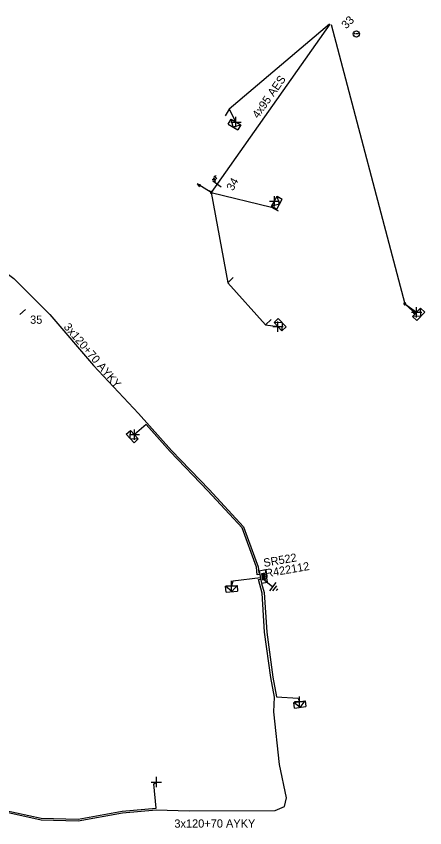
# Model space of a CAD drawing. Extents: x -540247 to -537390, y -1183890 to -1180355.
# Drawn here: x -537857 to -537807.3, y -1180518 to -1180419.2 of the extents above; entities that cross this region are included whole.
import ezdxf

# ---------------------------------------------------------------- set-up
doc = ezdxf.new("R2010")
doc.units = 0
for name, color, linetype in [('Vrstva 1', 7, 'Continuous'), ('Vrstva 10', 7, 'Continuous'), ('Vrstva 13', 7, 'Continuous'), ('Vrstva 14', 7, 'Continuous'), ('Vrstva 15', 7, 'Continuous'), ('Vrstva 18', 7, 'Continuous'), ('Vrstva 2', 7, 'Continuous'), ('Vrstva 28', 7, 'Continuous'), ('Vrstva 29', 7, 'Continuous'), ('Vrstva 30', 7, 'Continuous'), ('Vrstva 31', 7, 'Continuous'), ('Vrstva 34', 7, 'Continuous'), ('Vrstva 36', 7, 'Continuous'), ('Vrstva 4', 7, 'Continuous'), ('Vrstva 5', 7, 'Continuous'), ('Vrstva 50', 7, 'Continuous'), ('Vrstva 51', 7, 'Continuous'), ('Vrstva 52', 7, 'Continuous'), ('Vrstva 6', 7, 'Continuous'), ('Vrstva 8', 7, 'Continuous'), ('Vrstva 9', 7, 'Continuous')]:
    doc.layers.add(name, color=color, linetype=linetype)

# ---------------------------------------------------------------- blocks, each defined once
blk = doc.blocks.new('NN560')
at = {"layer": 'Vrstva 2'}
for points in [[(1.999, -0.001), (1.59, 0.141)], [(0, -0.001), (1.999, -0.001)], [(1.999, -0.001), (1.59, -0.134)]]:
    blk.add_lwpolyline(points, dxfattribs=at)
blk = doc.blocks.new('NN840')
at = {"layer": 'Vrstva 15'}
for points in [[(0.003, 0.619), (0.003, -0.631)], [(-0.745, -0.71), (-0.745, -0.66)], [(-0.73, -0.764), (-0.745, -0.71)], [(-0.657, -0.798), (-0.73, -0.764)], [(-0.627, -0.798), (-0.657, -0.798)], [(-0.558, -0.764), (-0.627, -0.798)], [(-0.538, -0.71), (-0.558, -0.764)], [(-0.538, -0.385), (-0.538, -0.71)], [(-0.332, -0.385), (-0.332, -0.798)], [(-0.332, -0.641), (-0.125, -0.385)], [(-0.263, -0.557), (-0.091, -0.798)]]:
    blk.add_lwpolyline(points, dxfattribs=at)
blk = doc.blocks.new('NN770')
at = {"layer": 'Vrstva 10'}
for p, q in [((0.002, 0.187), (0.002, 0.263)), ((0.002, -0.276), (0.002, 0.111))]:
    blk.add_line(p, q, dxfattribs=at)
blk.add_circle((0, -0.008), 0.375, dxfattribs=at)
blk = doc.blocks.new('NN800')
at = {"layer": 'Vrstva 1'}
for points in [[(-0.442, 0.442), (0.442, -0.442)], [(-0.442, -0.442), (0.442, 0.442)]]:
    blk.add_lwpolyline(points, dxfattribs=at)
blk = doc.blocks.new('NN620')
at = {"layer": 'Vrstva 8'}
for points in [[(0.752, 0.004), (-0.748, 0.004)], [(-0.748, 0.004), (-0.748, -0.746)], [(0.752, -0.746), (0.752, 0.004)], [(-0.748, -0.746), (0.752, -0.746)], [(0.368, -0.18), (-0.376, -0.18)], [(-0.376, -0.18), (-0.376, -0.558)], [(-0.376, -0.558), (0.368, -0.558)], [(0.321, -0.227), (-0.329, -0.227)], [(-0.329, -0.227), (-0.329, -0.51)], [(-0.329, -0.51), (0.321, -0.51)], [(0.274, -0.274), (-0.281, -0.274)], [(-0.281, -0.274), (-0.281, -0.463)], [(-0.281, -0.463), (0.274, -0.463)], [(0.227, -0.321), (-0.234, -0.321)], [(-0.234, -0.321), (-0.234, -0.416)], [(-0.234, -0.416), (0.227, -0.416)], [(-0.193, -0.369), (0.185, -0.369)], [(0.227, -0.416), (0.227, -0.321)], [(0.274, -0.463), (0.274, -0.274)], [(0.321, -0.51), (0.321, -0.227)], [(0.368, -0.558), (0.368, -0.18)]]:
    blk.add_lwpolyline(points, dxfattribs=at)
blk = doc.blocks.new('NN630')
at = {"layer": 'Vrstva 9'}
for points in [[(-0.003, -0.7), (-0.703, 0)], [(-0.703, -0.7), (-0.703, 0), (0.697, 0), (0.697, -0.7)], [(-0.703, -0.7), (0.697, -0.7)], [(-0.003, -0.7), (0.697, 0)]]:
    blk.add_lwpolyline(points, dxfattribs=at)
blk = doc.blocks.new('NN810')
at = {"layer": 'Vrstva 14'}
for points in [[(0.004, -0.64), (0.004, -1.89)], [(0.629, -1.89), (-0.621, -1.89)], [(0.388, -2.2), (-0.399, -2.2)], [(0.004, -2.515), (-0.124, -2.515)], [(0.137, -2.515), (0.004, -2.515)]]:
    blk.add_lwpolyline(points, dxfattribs=at)
blk = doc.blocks.new('NN500')
at = {"layer": 'Vrstva 2'}
for points in [[(0, -0.24), (0.02, -0.23), (0.05, -0.23), (0.07, -0.22), (0.09, -0.22), (0.12, -0.2), (0.14, -0.19), (0.16, -0.18), (0.17, -0.16), (0.19, -0.14), (0.2, -0.12), (0.21, -0.1), (0.22, -0.07), (0.23, -0.05), (0.23, -0.02), (0.23, 0), (0.23, 0.02), (0.23, 0.05), (0.22, 0.07), (0.21, 0.1), (0.2, 0.12), (0.19, 0.14), (0.17, 0.16), (0.16, 0.17), (0.14, 0.19), (0.12, 0.2), (0.09, 0.21), (0.07, 0.22), (0.05, 0.23), (0.02, 0.23), (0, 0.23), (-0.03, 0.23), (-0.05, 0.23), (-0.07, 0.22), (-0.1, 0.21), (-0.12, 0.2), (-0.14, 0.19), (-0.16, 0.17), (-0.18, 0.16), (-0.19, 0.14), (-0.2, 0.12), (-0.22, 0.1), (-0.22, 0.07), (-0.23, 0.05), (-0.23, 0.02), (-0.24, 0), (-0.23, -0.02), (-0.23, -0.05), (-0.22, -0.07), (-0.22, -0.1), (-0.2, -0.12), (-0.19, -0.14), (-0.18, -0.16), (-0.16, -0.18), (-0.14, -0.19), (-0.12, -0.2), (-0.1, -0.22), (-0.07, -0.22), (-0.05, -0.23), (-0.03, -0.23), (0, -0.24)], [(0, -0.24), (0.02, -0.23), (0.05, -0.23), (0.07, -0.22), (0.09, -0.22), (0.12, -0.2), (0.14, -0.19), (0.16, -0.18), (0.17, -0.16), (0.19, -0.14), (0.2, -0.12), (0.21, -0.1), (0.22, -0.07), (0.23, -0.05), (0.23, -0.02), (0.23, 0), (0.23, 0.02), (0.23, 0.05), (0.22, 0.07), (0.21, 0.1), (0.2, 0.12), (0.19, 0.14), (0.17, 0.16), (0.16, 0.17), (0.14, 0.19), (0.12, 0.2), (0.09, 0.21), (0.07, 0.22), (0.05, 0.23), (0.02, 0.23), (0, 0.23), (-0.03, 0.23), (-0.05, 0.23), (-0.07, 0.22), (-0.1, 0.21), (-0.12, 0.2), (-0.14, 0.19), (-0.16, 0.17), (-0.18, 0.16), (-0.19, 0.14), (-0.2, 0.12), (-0.22, 0.1), (-0.22, 0.07), (-0.23, 0.05), (-0.23, 0.02), (-0.24, 0), (-0.23, -0.02), (-0.23, -0.05), (-0.22, -0.07), (-0.22, -0.1), (-0.2, -0.12), (-0.19, -0.14), (-0.18, -0.16), (-0.16, -0.18), (-0.14, -0.19), (-0.12, -0.2), (-0.1, -0.22), (-0.07, -0.22), (-0.05, -0.23), (-0.03, -0.23), (0, -0.24)], [(0, -0.21), (0.02, -0.2), (0.04, -0.2), (0.06, -0.2), (0.08, -0.19), (0.1, -0.18), (0.12, -0.17), (0.14, -0.15), (0.15, -0.14), (0.16, -0.12), (0.18, -0.1), (0.19, -0.08), (0.19, -0.06), (0.2, -0.04), (0.2, -0.02), (0.2, 0), (0.2, 0.02), (0.2, 0.04), (0.19, 0.06), (0.19, 0.08), (0.18, 0.1), (0.16, 0.12), (0.15, 0.14), (0.14, 0.15), (0.12, 0.17), (0.1, 0.18), (0.08, 0.19), (0.06, 0.19), (0.04, 0.2), (0.02, 0.2), (0, 0.2), (-0.02, 0.2), (-0.04, 0.2), (-0.06, 0.19), (-0.08, 0.19), (-0.1, 0.18), (-0.12, 0.17), (-0.14, 0.15), (-0.15, 0.14), (-0.17, 0.12), (-0.18, 0.1), (-0.19, 0.08), (-0.2, 0.06), (-0.2, 0.04), (-0.21, 0.02), (-0.21, 0), (-0.21, -0.02), (-0.2, -0.04), (-0.2, -0.06), (-0.19, -0.08), (-0.18, -0.1), (-0.17, -0.12), (-0.15, -0.14), (-0.14, -0.15), (-0.12, -0.17), (-0.1, -0.18), (-0.08, -0.19), (-0.06, -0.2), (-0.04, -0.2), (-0.02, -0.2), (0, -0.21)], [(0, -0.18), (0.02, -0.18), (0.04, -0.17), (0.05, -0.17), (0.07, -0.16), (0.09, -0.15), (0.1, -0.14), (0.12, -0.13), (0.13, -0.12), (0.14, -0.1), (0.15, -0.09), (0.16, -0.07), (0.17, -0.05), (0.17, -0.04), (0.17, -0.02), (0.17, 0), (0.17, 0.02), (0.17, 0.04), (0.17, 0.05), (0.16, 0.07), (0.15, 0.09), (0.14, 0.1), (0.13, 0.12), (0.12, 0.13), (0.1, 0.14), (0.09, 0.15), (0.07, 0.16), (0.05, 0.17), (0.04, 0.17), (0.02, 0.17), (0, 0.18), (-0.02, 0.17), (-0.04, 0.17), (-0.06, 0.17), (-0.07, 0.16), (-0.09, 0.15), (-0.1, 0.14), (-0.12, 0.13), (-0.13, 0.12), (-0.14, 0.1), (-0.15, 0.09), (-0.16, 0.07), (-0.17, 0.05), (-0.17, 0.04), (-0.18, 0.02), (-0.18, 0), (-0.18, -0.02), (-0.17, -0.04), (-0.17, -0.05), (-0.16, -0.07), (-0.15, -0.09), (-0.14, -0.1), (-0.13, -0.12), (-0.12, -0.13), (-0.1, -0.14), (-0.09, -0.15), (-0.07, -0.16), (-0.06, -0.17), (-0.04, -0.17), (-0.02, -0.18), (0, -0.18)], [(0, -0.15), (0.01, -0.15), (0.03, -0.14), (0.04, -0.14), (0.06, -0.13), (0.07, -0.13), (0.08, -0.12), (0.1, -0.11), (0.11, -0.1), (0.12, -0.09), (0.13, -0.07), (0.13, -0.06), (0.14, -0.05), (0.14, -0.03), (0.14, -0.02), (0.14, 0), (0.14, 0.01), (0.14, 0.03), (0.14, 0.04), (0.13, 0.06), (0.13, 0.07), (0.12, 0.09), (0.11, 0.1), (0.1, 0.11), (0.08, 0.12), (0.07, 0.13), (0.06, 0.13), (0.04, 0.14), (0.03, 0.14), (0.01, 0.14), (0, 0.15), (-0.02, 0.14), (-0.03, 0.14), (-0.05, 0.14), (-0.06, 0.13), (-0.07, 0.13), (-0.09, 0.12), (-0.1, 0.11), (-0.11, 0.1), (-0.12, 0.09), (-0.13, 0.07), (-0.13, 0.06), (-0.14, 0.04), (-0.14, 0.03), (-0.15, 0.01), (-0.15, 0), (-0.15, -0.02), (-0.14, -0.03), (-0.14, -0.05), (-0.13, -0.06), (-0.13, -0.07), (-0.12, -0.09), (-0.11, -0.1), (-0.1, -0.11), (-0.09, -0.12), (-0.07, -0.13), (-0.06, -0.13), (-0.05, -0.14), (-0.03, -0.14), (-0.02, -0.15), (0, -0.15)], [(0, -0.12), (0.01, -0.12), (0.02, -0.11), (0.03, -0.11), (0.05, -0.11), (0.06, -0.1), (0.07, -0.09), (0.08, -0.09), (0.09, -0.08), (0.09, -0.07), (0.1, -0.06), (0.11, -0.05), (0.11, -0.04), (0.11, -0.02), (0.11, -0.01), (0.12, 0), (0.11, 0.01), (0.11, 0.02), (0.11, 0.04), (0.11, 0.05), (0.1, 0.06), (0.09, 0.07), (0.09, 0.08), (0.08, 0.09), (0.07, 0.09), (0.06, 0.1), (0.05, 0.11), (0.03, 0.11), (0.02, 0.11), (0.01, 0.12), (0, 0.12), (-0.01, 0.12), (-0.03, 0.11), (-0.04, 0.11), (-0.05, 0.11), (-0.06, 0.1), (-0.07, 0.09), (-0.08, 0.09), (-0.09, 0.08), (-0.1, 0.07), (-0.1, 0.06), (-0.11, 0.05), (-0.11, 0.04), (-0.12, 0.02), (-0.12, 0.01), (-0.12, 0), (-0.12, -0.01), (-0.12, -0.02), (-0.11, -0.04), (-0.11, -0.05), (-0.1, -0.06), (-0.1, -0.07), (-0.09, -0.08), (-0.08, -0.09), (-0.07, -0.09), (-0.06, -0.1), (-0.05, -0.11), (-0.04, -0.11), (-0.03, -0.11), (-0.01, -0.12), (0, -0.12)], [(0, -0.09), (0.01, -0.09), (0.02, -0.09), (0.03, -0.08), (0.03, -0.08), (0.04, -0.08), (0.05, -0.07), (0.06, -0.07), (0.06, -0.06), (0.07, -0.05), (0.07, -0.04), (0.08, -0.04), (0.08, -0.03), (0.08, -0.02), (0.09, -0.01), (0.09, 0), (0.09, 0.01), (0.08, 0.02), (0.08, 0.03), (0.08, 0.03), (0.07, 0.04), (0.07, 0.05), (0.06, 0.06), (0.06, 0.06), (0.05, 0.07), (0.04, 0.07), (0.03, 0.08), (0.03, 0.08), (0.02, 0.08), (0.01, 0.09), (0, 0.09), (-0.01, 0.09), (-0.02, 0.08), (-0.03, 0.08), (-0.04, 0.08), (-0.04, 0.07), (-0.05, 0.07), (-0.06, 0.06), (-0.07, 0.06), (-0.07, 0.05), (-0.08, 0.04), (-0.08, 0.03), (-0.08, 0.03), (-0.09, 0.02), (-0.09, 0.01), (-0.09, 0), (-0.09, -0.01), (-0.09, -0.02), (-0.08, -0.03), (-0.08, -0.04), (-0.08, -0.04), (-0.07, -0.05), (-0.07, -0.06), (-0.06, -0.07), (-0.05, -0.07), (-0.04, -0.08), (-0.04, -0.08), (-0.03, -0.08), (-0.02, -0.09), (-0.01, -0.09), (0, -0.09)], [(0, -0.06), (0, -0.06), (0.01, -0.06), (0.02, -0.05), (0.02, -0.05), (0.03, -0.05), (0.03, -0.05), (0.04, -0.04), (0.04, -0.04), (0.05, -0.03), (0.05, -0.03), (0.05, -0.02), (0.05, -0.02), (0.05, -0.01), (0.06, -0.01), (0.06, 0), (0.06, 0.01), (0.05, 0.01), (0.05, 0.02), (0.05, 0.02), (0.05, 0.03), (0.05, 0.03), (0.04, 0.04), (0.04, 0.04), (0.03, 0.05), (0.03, 0.05), (0.02, 0.05), (0.02, 0.05), (0.01, 0.06), (0, 0.06), (0, 0.06), (-0.01, 0.06), (-0.01, 0.06), (-0.02, 0.05), (-0.02, 0.05), (-0.03, 0.05), (-0.03, 0.05), (-0.04, 0.04), (-0.04, 0.04), (-0.05, 0.03), (-0.05, 0.03), (-0.05, 0.02), (-0.06, 0.02), (-0.06, 0.01), (-0.06, 0.01), (-0.06, 0), (-0.06, -0.01), (-0.06, -0.01), (-0.06, -0.02), (-0.05, -0.02), (-0.05, -0.03), (-0.05, -0.03), (-0.04, -0.04), (-0.04, -0.04), (-0.03, -0.05), (-0.03, -0.05), (-0.02, -0.05), (-0.02, -0.05), (-0.01, -0.06), (-0.01, -0.06), (0, -0.06)], [(0, -0.03), (0, -0.03), (0, -0.03), (0.01, -0.03), (0.01, -0.03), (0.01, -0.02), (0.02, -0.02), (0.02, -0.02), (0.02, -0.02), (0.02, -0.02), (0.02, -0.01), (0.02, -0.01), (0.03, -0.01), (0.03, -0.01), (0.03, 0), (0.03, 0), (0.03, 0), (0.03, 0.01), (0.03, 0.01), (0.02, 0.01), (0.02, 0.01), (0.02, 0.02), (0.02, 0.02), (0.02, 0.02), (0.02, 0.02), (0.01, 0.02), (0.01, 0.02), (0.01, 0.03), (0, 0.03), (0, 0.03), (0, 0.03), (0, 0.03), (-0.01, 0.03), (-0.01, 0.03), (-0.01, 0.02), (-0.02, 0.02), (-0.02, 0.02), (-0.02, 0.02), (-0.02, 0.02), (-0.02, 0.02), (-0.03, 0.01), (-0.03, 0.01), (-0.03, 0.01), (-0.03, 0.01), (-0.03, 0), (-0.03, 0), (-0.03, 0), (-0.03, -0.01), (-0.03, -0.01), (-0.03, -0.01), (-0.03, -0.01), (-0.02, -0.02), (-0.02, -0.02), (-0.02, -0.02), (-0.02, -0.02), (-0.02, -0.02), (-0.01, -0.03), (-0.01, -0.03), (-0.01, -0.03), (0, -0.03), (0, -0.03)], [(0.23, 0), (0.7, 0)]]:
    blk.add_lwpolyline(points, dxfattribs=at)
blk = doc.blocks.new('NN510')
at = {"layer": 'Vrstva 2'}
blk.add_lwpolyline([(0.001, 0.002), (0.001, 0.939)], dxfattribs=at)

msp = doc.modelspace()

# ---------------------------------------------------------------- linework, layer by layer
at = {"layer": 'Vrstva 4'}
for points in [[(-537818.884, -1180420.138), (-537831.082, -1180430.502), (-537830.253, -1180432.05)], [(-537818.663, -1180420.172), (-537809.71, -1180454.17), (-537808.264, -1180455.208)]]:
    msp.add_lwpolyline(points, dxfattribs=at)
at = {"layer": 'Vrstva 5'}
for points in [[(-537884.586, -1180432.61), (-537882.08, -1180433.9), (-537880.81, -1180434.99), (-537875.1, -1180439.06), (-537872.09, -1180441.05), (-537866.46, -1180444.78), (-537862.96, -1180446.83), (-537857.29, -1180451.1), (-537852.89, -1180455.49), (-537847.58, -1180461.71), (-537842.1, -1180467.52), (-537838.1, -1180472.04), (-537833.53, -1180476.8), (-537829.32, -1180481.34), (-537827.56, -1180486.21), (-537827.489, -1180486.953), (-537827.363, -1180486.926)], [(-537866.535, -1180513.177), (-537866.577, -1180514.907), (-537865.85, -1180515.36), (-537858.5, -1180516.01), (-537853.98, -1180517), (-537849.45, -1180517.13), (-537844.07, -1180516.16), (-537839.96, -1180515.78), (-537835.96, -1180515.9), (-537825.48, -1180515.88), (-537824.36, -1180515.37), (-537824.1, -1180514.31), (-537824.95, -1180510.27), (-537825.63, -1180503.87), (-537825.563, -1180502.073), (-537826.013, -1180499.69), (-537826.764, -1180494.172), (-537827.064, -1180489.391), (-537827.53, -1180487.764), (-537827.266, -1180487.689)]]:
    msp.add_lwpolyline(points, dxfattribs=at)
at = {"layer": 'Vrstva 50'}
msp.add_lwpolyline([(-537818.821, -1180420.147), (-537833.255, -1180440.612)], dxfattribs=at)
at = {"layer": 'Vrstva 52'}
for points in [[(-537827.321, -1180487.122), (-537827.667, -1180487.196), (-537827.757, -1180486.254), (-537829.494, -1180481.446), (-537833.675, -1180476.937), (-537838.247, -1180472.176), (-537841.175, -1180468.869), (-537842.608, -1180470.113)], [(-537827.272, -1180487.539), (-537830.632, -1180487.957), (-537830.809, -1180488.524)], [(-537827.141, -1180488.215), (-537826.816, -1180489.349), (-537826.516, -1180494.148), (-537825.767, -1180499.65), (-537825.317, -1180502.027), (-537822.678, -1180502.213), (-537822.52, -1180502.62)], [(-537866.335, -1180513.182), (-537866.374, -1180514.798), (-537865.785, -1180515.165), (-537858.47, -1180515.812), (-537853.956, -1180516.801), (-537849.465, -1180516.929), (-537844.097, -1180515.962), (-537839.966, -1180515.58), (-537840.238, -1180512.609), (-537839.947, -1180512.41)]]:
    msp.add_lwpolyline(points, dxfattribs=at)
at = {"layer": 'Vrstva 8'}
for points in [[(-537833.255, -1180440.612), (-537831.264, -1180451.625), (-537826.672, -1180456.737), (-537825.149, -1180456.955)], [(-537833.255, -1180440.612), (-537825.95, -1180442.414), (-537825.567, -1180441.692)]]:
    msp.add_lwpolyline(points, dxfattribs=at)

# ---------------------------------------------------------------- block references
at = {"layer": 'Vrstva 13'}
for name, p, rotation in [('NN510', (-537831.081, -1180430.502), 149.20328602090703), ('NN560', (-537833.256, -1180440.612), 149.28067207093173), ('NN510', (-537825.95, -1180442.413), -119.28188058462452), ('NN510', (-537831.265, -1180451.625), -45.20068887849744), ('NN560', (-537809.71, -1180454.17), -43.16770277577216), ('NN510', (-537855.879, -1180454.867), 132.18644449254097), ('NN510', (-537826.672, -1180456.737), -47.28672215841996)]:
    msp.add_blockref(name, p, dxfattribs=dict(at, rotation=rotation))
at = {"layer": 'Vrstva 13', "xscale": 0.5}
for p, yscale, rotation in [((-537833.255, -1180440.612), 0.5, 149.20700002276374), ((-537809.71, -1180454.17), 0.5000000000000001, -44.10400000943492)]:
    msp.add_blockref('NN500', p, dxfattribs=dict(at, yscale=yscale, rotation=rotation))
at = {"layer": 'Vrstva 15', "rotation": 52.02628610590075}
msp.add_blockref('NN810', (-537827.281, -1180487.454), dxfattribs=at)
at = {"layer": 'Vrstva 18', "rotation": -125.19533332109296}
msp.add_blockref('NN840', (-537832.563, -1180439.632), dxfattribs=at)
at = {"layer": 'Vrstva 28', "rotation": 99.86143057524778}
msp.add_blockref('NN620', (-537827.281, -1180487.453), dxfattribs=at)
at = {"layer": 'Vrstva 31'}
for p, rotation in [((-537830.253, -1180432.051), -30.782608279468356), ((-537825.567, -1180441.692), 60.71811948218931), ((-537808.264, -1180455.208), 45.89606664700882), ((-537825.149, -1180456.955), 132.7132777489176), ((-537842.608, -1180470.113), -47.62218052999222), ((-537830.809, -1180488.524), 3.9469666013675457), ((-537822.52, -1180502.62), 7.169327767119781)]:
    msp.add_blockref('NN630', p, dxfattribs=dict(at, rotation=rotation))
at = {"layer": 'Vrstva 34'}
for p, rotation in [((-537830.253, -1180432.05), 45), ((-537825.567, -1180441.691), 45), ((-537808.264, -1180455.208), 45), ((-537825.149, -1180456.955), 45), ((-537842.608, -1180470.113), 45), ((-537830.809, -1180488.524), 45), ((-537822.52, -1180502.619), 45.00000009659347), ((-537839.947, -1180512.41), 45)]:
    msp.add_blockref('NN800', p, dxfattribs=dict(at, rotation=rotation))
at = {"layer": 'Vrstva 36', "rotation": 90}
msp.add_blockref('NN770', (-537815.609, -1180421.325), dxfattribs=at)

# ---------------------------------------------------------------- texts
at = {"layer": 'Vrstva 14'}
for s, rotation, p in [('33', 45.014, (-537816.831, -1180420.781)), ('34', 61.135, (-537830.615, -1180440.5))]:
    msp.add_text(s, height=1, rotation=rotation, dxfattribs=at).set_placement(p)
msp.add_text('35', height=1, dxfattribs=at).set_placement((-537855.31, -1180456.612))
at = {"layer": 'Vrstva 29'}
msp.add_text('R422112', height=1, rotation=9.861, dxfattribs=at).set_placement((-537826.602, -1180487.504))
at = {"layer": 'Vrstva 30'}
msp.add_text('SR522', height=1, rotation=9.861, dxfattribs=at).set_placement((-537826.824, -1180486.224))
at = {"layer": 'Vrstva 51'}
msp.add_text('4x95 AES', height=1, rotation=54.805, dxfattribs=at).set_placement((-537827.561, -1180431.691))
at = {"layer": 'Vrstva 6'}
for rotation, p in [(310.487, (-537851.289, -1180457.035)), (0.109, (-537837.752, -1180517.958))]:
    msp.add_text('3x120+70 AYKY', height=1, rotation=rotation, dxfattribs=at).set_placement(p)

doc.saveas('drawing.dxf')
